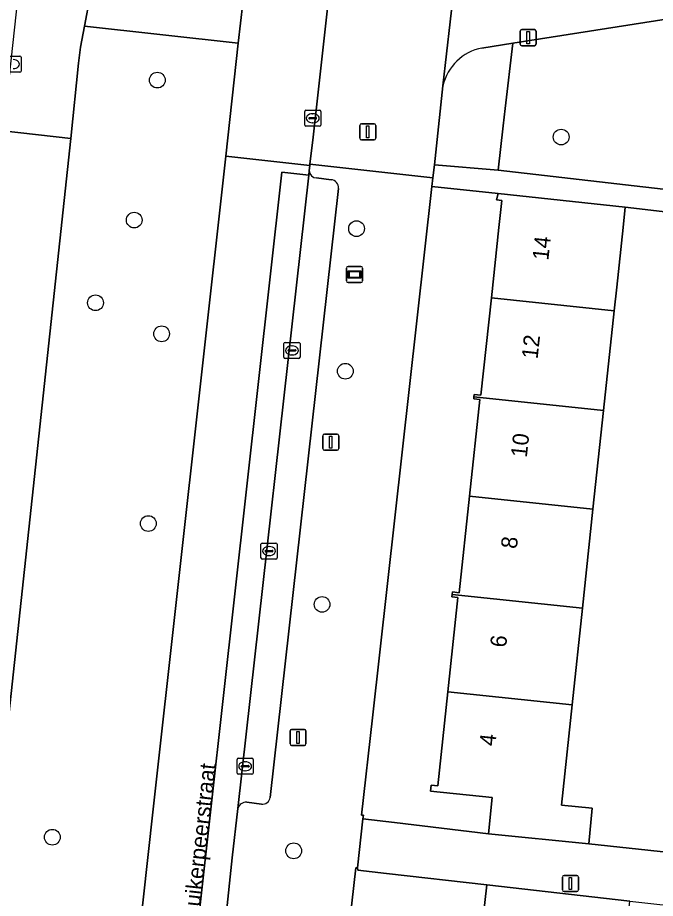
# Model space of a CAD drawing. Extents: x 162026 to 163502, y 387295 to 388169.
# Drawn here: x 162355 to 162394.6, y 387458.3 to 387513 of the extents above; entities that cross this region are included whole.
import ezdxf

# ---------------------------------------------------------------- set-up
doc = ezdxf.new("R2010")
doc.units = 0
for name, color, linetype in [('IMGEO_Berm_groen', 7, 'Continuous'), ('IMGEO_Boom', 7, 'Continuous'), ('IMGEO_Erf', 7, 'Continuous'), ('IMGEO_Fietspad_gesloten', 7, 'Continuous'), ('IMGEO_Groenvoorziening', 7, 'Continuous'), ('IMGEO_Hek', 7, 'Continuous'), ('IMGEO_Informatiebord', 7, 'Continuous'), ('IMGEO_Kolk', 7, 'Continuous'), ('IMGEO_Lichtmast', 7, 'Continuous'), ('IMGEO_Openbare_ruimte_label', 7, 'Continuous'), ('IMGEO_Pand', 7, 'Continuous'), ('IMGEO_Pand_nummerreeks', 7, 'Continuous'), ('IMGEO_Parkeervlak_open', 7, 'Continuous'), ('IMGEO_Rijbaan_lokaal_gesloten', 7, 'Continuous'), ('IMGEO_Voetpad_open', 7, 'Continuous')]:
    doc.layers.add(name, color=color, linetype=linetype)

msp = doc.modelspace()

# ---------------------------------------------------------------- linework, layer by layer
at = {"layer": 'IMGEO_Berm_groen'}
for points in [[(162367.963, 387504.443), (162368.74, 387511.448), (162359.196, 387512.511), (162358.952, 387511.213), (162358.817, 387510.216), (162358.349, 387505.53), (162353.961, 387464.714), (162349.86, 387427.109)], [(162361.255, 387443.988), (162363.465, 387463.887), (162367.963, 387504.443)]]:
    msp.add_lwpolyline(points, dxfattribs=at)
at = {"layer": 'IMGEO_Boom'}
for centre in [(162363.715, 387509.161), (162388.781, 387505.624), (162362.28, 387500.467), (162376.081, 387499.936), (162359.877, 387495.33), (162363.979, 387493.402), (162375.381, 387491.078), (162363.153, 387481.618), (162373.94, 387476.596), (162357.195, 387462.136), (162372.176, 387461.291)]:
    msp.add_circle(centre, 0.489, dxfattribs=at)
at = {"layer": 'IMGEO_Erf'}
msp.add_lwpolyline([(162383.737, 387489.316), (162383.352, 387489.357), (162383.367, 387489.498), (162383.382, 387489.641), (162383.805, 387489.596), (162384.45, 387495.645), (162384.914, 387500), (162385.095, 387501.693), (162384.765, 387501.728), (162384.875, 387502.11), (162380.76, 387502.548), (162377.073, 387469.561), (162376.396, 387463.513), (162376.503, 387463.509), (162376.477, 387463.277), (162378.441, 387463.04), (162384.272, 387462.336), (162384.492, 387464.596), (162380.664, 387465.004), (162380.704, 387465.377), (162381.127, 387465.332), (162381.75, 387471.175), (162382.373, 387477.018), (162382.003, 387477.058), (162382.02, 387477.215), (162382.037, 387477.369), (162382.459, 387477.324), (162383.098, 387483.32)], close=True, dxfattribs=at)
for points in [[(162399.996, 387500.421), (162392.758, 387501.269), (162392.623, 387500), (162392.228, 387496.298), (162392.072, 387494.832), (162391.411, 387488.64), (162390.757, 387482.503), (162390.101, 387476.353), (162389.461, 387470.353), (162388.798, 387464.131), (162390.708, 387463.945), (162390.492, 387461.729), (162395.498, 387461.182)], [(162377.752, 387439.384), (162379.017, 387439.241), (162379.247, 387441.236), (162378.017, 387441.378), (162378.471, 387445.326), (162378.919, 387449.221), (162380.223, 387449.071), (162380.463, 387451.159), (162381.147, 387457.113), (162383.889, 387456.798), (162384.164, 387459.183), (162377.94, 387459.884), (162376.15, 387460.086), (162376.131, 387460.234), (162376.03, 387460.239), (162375.655, 387456.942), (162371.134, 387416.396)]]:
    msp.add_lwpolyline(points, dxfattribs=at)
at = {"layer": 'IMGEO_Fietspad_gesloten'}
msp.add_lwpolyline([(162367.941, 387456.884), (162367.962, 387457.104), (162368.361, 387460.854), (162368.714, 387463.921), (162373.113, 387503.254), (162371.444, 387503.441), (162363.403, 387431.184)], dxfattribs=at)
at = {"layer": 'IMGEO_Groenvoorziening'}
msp.add_lwpolyline([(162404.551, 387514.406), (162385.791, 387511.457), (162385.309, 387507.39), (162385.183, 387506.312), (162384.868, 387503.561), (162403.028, 387501.478)], close=True, dxfattribs=at)
for points in [[(162385.309, 387507.39), (162385.791, 387511.457), (162383.865, 387511.154)], [(162381.44, 387508.812), (162380.999, 387504.686), (162380.911, 387503.894), (162384.868, 387503.561), (162385.183, 387506.312), (162385.309, 387507.39)]]:
    msp.add_lwpolyline(points, dxfattribs=at)
msp.add_arc((162384.455, 387508.117), 3.094, 100.9859, 167.0191, dxfattribs=at)
at = {"layer": 'IMGEO_Hek'}
msp.add_lwpolyline([(162384.868, 387503.561), (162385.791, 387511.457)], dxfattribs=at)
at = {"layer": 'IMGEO_Informatiebord'}
for p, q in [((162375.458, 387496.685), (162375.458, 387497.485)), ((162375.458, 387497.485), (162375.458, 387496.685)), ((162375.558, 387497.585), (162376.348, 387497.585)), ((162376.348, 387497.585), (162375.558, 387497.585)), ((162376.448, 387497.485), (162376.448, 387496.685)), ((162376.448, 387496.685), (162376.448, 387497.485)), ((162376.348, 387496.585), (162375.558, 387496.585)), ((162375.558, 387496.585), (162376.348, 387496.585))]:
    msp.add_line(p, q, dxfattribs=at)
for points in [[(162375.559, 387497.317), (162376.347, 387497.317), (162376.347, 387496.853), (162375.559, 387496.853), (162375.559, 387497.317)], [(162375.624, 387497.252), (162375.624, 387496.918), (162376.282, 387496.918), (162376.282, 387497.252), (162375.624, 387497.252)]]:
    msp.add_lwpolyline(points, dxfattribs=at)
for centre, start, end in [((162375.558, 387497.485), 90, 180), ((162375.558, 387497.485), 90, 180), ((162376.348, 387497.485), 0, 90), ((162376.348, 387497.485), 360, 90), ((162375.558, 387496.685), 180, 270), ((162375.558, 387496.685), 180, 270), ((162376.348, 387496.685), 270, 0), ((162376.348, 387496.685), 270, 0)]:
    msp.add_arc(centre, 0.1, start, end, dxfattribs=at)
at = {"layer": 'IMGEO_Kolk'}
for p, q in [((162354.327, 387510.652), (162355.179, 387510.652)), ((162355.253, 387510.578), (162355.253, 387509.726)), ((162355.179, 387509.652), (162354.327, 387509.652)), ((162372.861, 387506.367), (162372.861, 387507.219)), ((162372.936, 387507.293), (162373.788, 387507.293)), ((162373.862, 387507.219), (162373.862, 387506.367)), ((162373.12, 387506.787), (162373.12, 387506.799)), ((162373.558, 387506.75), (162373.16, 387506.75)), ((162373.163, 387506.836), (162373.561, 387506.836)), ((162373.349, 387507.073), (162373.374, 387507.073)), ((162373.604, 387506.799), (162373.604, 387506.787)), ((162373.788, 387506.293), (162372.936, 387506.293)), ((162373.372, 387506.513), (162373.347, 387506.513)), ((162371.569, 387491.945), (162371.569, 387492.797)), ((162371.644, 387492.871), (162372.496, 387492.871)), ((162372.057, 387492.651), (162372.082, 387492.651)), ((162372.57, 387492.797), (162372.57, 387491.945)), ((162371.828, 387492.365), (162371.828, 387492.377)), ((162372.266, 387492.328), (162371.868, 387492.328)), ((162371.871, 387492.414), (162372.269, 387492.414)), ((162372.08, 387492.091), (162372.055, 387492.091)), ((162372.312, 387492.377), (162372.312, 387492.365)), ((162372.496, 387491.871), (162371.644, 387491.871)), ((162370.222, 387480.409), (162371.074, 387480.409)), ((162370.147, 387479.483), (162370.147, 387480.335)), ((162370.406, 387479.903), (162370.406, 387479.915)), ((162370.844, 387479.866), (162370.446, 387479.866)), ((162370.449, 387479.952), (162370.847, 387479.952)), ((162370.635, 387480.189), (162370.66, 387480.189)), ((162370.89, 387479.915), (162370.89, 387479.903)), ((162371.148, 387480.335), (162371.148, 387479.483)), ((162371.074, 387479.409), (162370.222, 387479.409)), ((162370.658, 387479.629), (162370.633, 387479.629)), ((162368.663, 387466.118), (162368.663, 387466.97)), ((162368.738, 387467.044), (162369.59, 387467.044)), ((162369.151, 387466.824), (162369.176, 387466.824)), ((162369.664, 387466.97), (162369.664, 387466.118)), ((162368.922, 387466.538), (162368.922, 387466.55)), ((162369.36, 387466.501), (162368.962, 387466.501)), ((162368.965, 387466.587), (162369.363, 387466.587)), ((162369.174, 387466.264), (162369.149, 387466.264)), ((162369.406, 387466.55), (162369.406, 387466.538)), ((162369.59, 387466.044), (162368.738, 387466.044))]:
    msp.add_line(p, q, dxfattribs=at)
for points in [[(162354.327, 387510.652), (162355.179, 387510.652)], [(162355.253, 387510.578), (162355.253, 387509.726)], [(162355.179, 387509.652), (162354.327, 387509.652)], [(162372.861, 387506.367), (162372.861, 387507.219)], [(162372.936, 387507.293), (162373.788, 387507.293)], [(162373.862, 387507.219), (162373.862, 387506.367)], [(162373.788, 387506.293), (162372.936, 387506.293)], [(162371.569, 387491.945), (162371.569, 387492.797)], [(162371.644, 387492.871), (162372.496, 387492.871)], [(162372.57, 387492.797), (162372.57, 387491.945)], [(162372.496, 387491.871), (162371.644, 387491.871)], [(162370.222, 387480.409), (162371.074, 387480.409)], [(162370.147, 387479.483), (162370.147, 387480.335)], [(162371.148, 387480.335), (162371.148, 387479.483)], [(162371.074, 387479.409), (162370.222, 387479.409)], [(162368.663, 387466.118), (162368.663, 387466.97)], [(162368.738, 387467.044), (162369.59, 387467.044)], [(162369.664, 387466.97), (162369.664, 387466.118)], [(162369.59, 387466.044), (162368.738, 387466.044)]]:
    msp.add_lwpolyline(points, dxfattribs=at)
for centre, radius, start, end in [((162355.177, 387510.576), 0.0765, 1.552, 88.448), ((162355.177, 387510.576), 0.0765, 1.552, 88.448), ((162355.177, 387509.728), 0.0765, 271.552, 358.448), ((162355.177, 387509.728), 0.0765, 271.552, 358.448), ((162372.938, 387507.217), 0.0765, 91.552, 178.448), ((162372.938, 387507.217), 0.0765, 91.552, 178.448), ((162373.786, 387507.217), 0.0765, 1.552, 88.448), ((162373.786, 387507.217), 0.0765, 1.552, 88.448), ((162373.16, 387506.796), 0.0403, 85.8775, 175.7526), ((162373.157, 387506.786), 0.0366, 178.938, 274.7102), ((162373.561, 387506.793), 0.043, 264.8664, 352.4533), ((162373.565, 387506.798), 0.0386, 1.7309, 96.639), ((162372.938, 387506.369), 0.0765, 181.552, 268.448), ((162372.938, 387506.369), 0.0765, 181.552, 268.448), ((162373.786, 387506.369), 0.0765, 271.552, 358.448), ((162373.786, 387506.369), 0.0765, 271.552, 358.448), ((162371.646, 387492.795), 0.0765, 91.552, 178.448), ((162371.646, 387492.795), 0.0765, 91.552, 178.448), ((162372.494, 387492.795), 0.0765, 1.552, 88.448), ((162372.494, 387492.795), 0.0765, 1.552, 88.448), ((162371.646, 387491.947), 0.0765, 181.552, 268.448), ((162371.646, 387491.947), 0.0765, 181.552, 268.448), ((162371.868, 387492.374), 0.0403, 85.8775, 175.7526), ((162371.865, 387492.364), 0.0366, 178.938, 274.7102), ((162372.269, 387492.371), 0.043, 264.8664, 352.4533), ((162372.273, 387492.376), 0.0386, 1.7309, 96.639), ((162372.494, 387491.947), 0.0765, 271.552, 358.448), ((162372.494, 387491.947), 0.0765, 271.552, 358.448), ((162370.224, 387480.333), 0.0765, 91.552, 178.448), ((162370.224, 387480.333), 0.0765, 91.552, 178.448), ((162371.072, 387480.333), 0.0765, 1.552, 88.448), ((162371.072, 387480.333), 0.0765, 1.552, 88.448), ((162370.446, 387479.912), 0.0403, 85.8775, 175.7526), ((162370.443, 387479.902), 0.0366, 178.938, 274.7102), ((162370.847, 387479.909), 0.043, 264.8664, 352.4533), ((162370.851, 387479.914), 0.0386, 1.7309, 96.639), ((162370.224, 387479.485), 0.0765, 181.552, 268.448), ((162370.224, 387479.485), 0.0765, 181.552, 268.448), ((162371.072, 387479.485), 0.0765, 271.552, 358.448), ((162371.072, 387479.485), 0.0765, 271.552, 358.448), ((162368.74, 387466.968), 0.0765, 91.552, 178.448), ((162368.74, 387466.968), 0.0765, 91.552, 178.448), ((162369.588, 387466.968), 0.0765, 1.552, 88.448), ((162369.588, 387466.968), 0.0765, 1.552, 88.448), ((162368.962, 387466.547), 0.0403, 85.8775, 175.7526), ((162368.959, 387466.537), 0.0366, 178.938, 274.7102), ((162369.363, 387466.544), 0.043, 264.8664, 352.4533), ((162369.367, 387466.549), 0.0386, 1.7309, 96.639), ((162368.74, 387466.12), 0.0765, 181.552, 268.448), ((162368.74, 387466.12), 0.0765, 181.552, 268.448), ((162369.588, 387466.12), 0.0765, 271.552, 358.448), ((162369.588, 387466.12), 0.0765, 271.552, 358.448)]:
    msp.add_arc(centre, radius, start, end, dxfattribs=at)
for centre, major_axis, ratio, start_param, end_param in [((162354.764, 387510.152), (-0.39, 0.002), 0.717154, 1.570796, 4.712389), ((162373.348, 387506.793), (-0.387, 0.002), 0.722429, 4.712389, 7.853982), ((162373.373, 387506.793), (-0.39, 0.002), 0.717154, 1.570796, 4.712389), ((162372.056, 387492.371), (-0.387, 0.002), 0.722429, 4.712389, 7.853982), ((162372.081, 387492.371), (-0.39, 0.002), 0.717154, 1.570796, 4.712389), ((162370.634, 387479.909), (-0.387, 0.002), 0.722429, 4.712389, 7.853982), ((162370.659, 387479.909), (-0.39, 0.002), 0.717154, 1.570796, 4.712389), ((162369.15, 387466.544), (-0.387, 0.002), 0.722429, 4.712389, 7.853982), ((162369.175, 387466.544), (-0.39, 0.002), 0.717154, 1.570796, 4.712389)]:
    msp.add_ellipse(centre, major_axis=major_axis, ratio=ratio, start_param=start_param, end_param=end_param, dxfattribs=at)
at = {"layer": 'IMGEO_Lichtmast'}
for p, q in [((162386.237, 387511.396), (162386.237, 387512.196)), ((162386.237, 387512.196), (162386.237, 387511.396)), ((162386.337, 387512.296), (162387.127, 387512.296)), ((162387.127, 387512.296), (162386.337, 387512.296)), ((162387.227, 387512.196), (162387.227, 387511.396)), ((162387.227, 387511.396), (162387.227, 387512.196)), ((162387.127, 387511.296), (162386.337, 387511.296)), ((162386.337, 387511.296), (162387.127, 387511.296)), ((162376.278, 387505.546), (162376.278, 387506.346)), ((162376.278, 387506.346), (162376.278, 387505.546)), ((162376.378, 387506.446), (162377.168, 387506.446)), ((162377.168, 387506.446), (162376.378, 387506.446)), ((162377.268, 387506.346), (162377.268, 387505.546)), ((162377.268, 387505.546), (162377.268, 387506.346)), ((162377.168, 387505.446), (162376.378, 387505.446)), ((162376.378, 387505.446), (162377.168, 387505.446)), ((162373.982, 387486.276), (162373.982, 387487.076)), ((162373.982, 387487.076), (162373.982, 387486.276)), ((162374.082, 387487.176), (162374.872, 387487.176)), ((162374.872, 387487.176), (162374.082, 387487.176)), ((162374.972, 387487.076), (162374.972, 387486.276)), ((162374.972, 387486.276), (162374.972, 387487.076)), ((162374.872, 387486.176), (162374.082, 387486.176)), ((162374.082, 387486.176), (162374.872, 387486.176)), ((162371.952, 387467.934), (162371.952, 387468.734)), ((162371.952, 387468.734), (162371.952, 387467.934)), ((162372.052, 387468.834), (162372.842, 387468.834)), ((162372.842, 387468.834), (162372.052, 387468.834)), ((162372.942, 387468.734), (162372.942, 387467.934)), ((162372.942, 387467.934), (162372.942, 387468.734)), ((162372.842, 387467.834), (162372.052, 387467.834)), ((162372.052, 387467.834), (162372.842, 387467.834)), ((162388.86, 387458.865), (162388.86, 387459.665)), ((162388.86, 387459.665), (162388.86, 387458.865)), ((162388.96, 387459.765), (162389.75, 387459.765)), ((162389.75, 387459.765), (162388.96, 387459.765)), ((162389.85, 387459.665), (162389.85, 387458.865)), ((162389.85, 387458.865), (162389.85, 387459.665)), ((162389.75, 387458.765), (162388.96, 387458.765)), ((162388.96, 387458.765), (162389.75, 387458.765))]:
    msp.add_line(p, q, dxfattribs=at)
for points in [[(162386.657, 387512.171), (162386.807, 387512.171), (162386.807, 387511.421), (162386.657, 387511.421), (162386.657, 387512.171)], [(162376.698, 387506.321), (162376.848, 387506.321), (162376.848, 387505.571), (162376.698, 387505.571), (162376.698, 387506.321)], [(162374.402, 387487.051), (162374.552, 387487.051), (162374.552, 387486.301), (162374.402, 387486.301), (162374.402, 387487.051)], [(162372.372, 387468.709), (162372.522, 387468.709), (162372.522, 387467.959), (162372.372, 387467.959), (162372.372, 387468.709)], [(162389.28, 387459.64), (162389.43, 387459.64), (162389.43, 387458.89), (162389.28, 387458.89), (162389.28, 387459.64)]]:
    msp.add_lwpolyline(points, dxfattribs=at)
for centre, start, end in [((162386.337, 387512.196), 90, 180), ((162386.337, 387512.196), 90, 180), ((162387.127, 387512.196), 0, 90), ((162387.127, 387512.196), 360, 90), ((162386.337, 387511.396), 180, 270), ((162386.337, 387511.396), 180, 270), ((162387.127, 387511.396), 270, 0), ((162387.127, 387511.396), 270, 0), ((162376.378, 387506.346), 90, 180), ((162376.378, 387506.346), 90, 180), ((162377.168, 387506.346), 0, 90), ((162377.168, 387506.346), 360, 90), ((162376.378, 387505.546), 180, 270), ((162376.378, 387505.546), 180, 270), ((162377.168, 387505.546), 270, 0), ((162377.168, 387505.546), 270, 0), ((162374.082, 387487.076), 90, 180), ((162374.082, 387487.076), 90, 180), ((162374.872, 387487.076), 0, 90), ((162374.872, 387487.076), 360, 90), ((162374.082, 387486.276), 180, 270), ((162374.082, 387486.276), 180, 270), ((162374.872, 387486.276), 270, 0), ((162374.872, 387486.276), 270, 0), ((162372.052, 387468.734), 90, 180), ((162372.052, 387468.734), 90, 180), ((162372.842, 387468.734), 0, 90), ((162372.842, 387468.734), 360, 90), ((162372.052, 387467.934), 180, 270), ((162372.052, 387467.934), 180, 270), ((162372.842, 387467.934), 270, 0), ((162372.842, 387467.934), 270, 0), ((162388.96, 387459.665), 90, 180), ((162388.96, 387459.665), 90, 180), ((162389.75, 387459.665), 0, 90), ((162389.75, 387459.665), 360, 90), ((162388.96, 387458.865), 180, 270), ((162388.96, 387458.865), 180, 270), ((162389.75, 387458.865), 270, 0), ((162389.75, 387458.865), 270, 0)]:
    msp.add_arc(centre, 0.1, start, end, dxfattribs=at)
at = {"layer": 'IMGEO_Pand'}
for points in [[(162392.072, 387494.832), (162392.228, 387496.298), (162392.623, 387500), (162392.758, 387501.269), (162384.875, 387502.11), (162384.765, 387501.728), (162385.095, 387501.693), (162384.914, 387500), (162384.45, 387495.645)], [(162391.411, 387488.64), (162392.072, 387494.832), (162384.45, 387495.645), (162383.805, 387489.596), (162383.382, 387489.641), (162383.367, 387489.498)], [(162383.367, 387489.498), (162383.352, 387489.357), (162383.737, 387489.316), (162383.098, 387483.32), (162390.757, 387482.503), (162391.411, 387488.64)], [(162383.098, 387483.32), (162382.459, 387477.324), (162382.037, 387477.369), (162382.02, 387477.215), (162390.101, 387476.353), (162390.757, 387482.503)], [(162389.461, 387470.353), (162390.101, 387476.353), (162382.02, 387477.215), (162382.003, 387477.058), (162382.373, 387477.018), (162381.75, 387471.175)], [(162390.492, 387461.729), (162390.708, 387463.945), (162388.798, 387464.131), (162389.461, 387470.353), (162381.75, 387471.175), (162381.127, 387465.332), (162380.704, 387465.377), (162380.664, 387465.004), (162384.492, 387464.596), (162384.272, 387462.336)], [(162392.061, 387455.86), (162392.771, 387455.778), (162393.046, 387458.163), (162384.164, 387459.183), (162383.889, 387456.798), (162381.147, 387457.113), (162380.463, 387451.159), (162388.505, 387450.25), (162391.38, 387449.925)]]:
    msp.add_lwpolyline(points, close=True, dxfattribs=at)
at = {"layer": 'IMGEO_Parkeervlak_open'}
for points in [[(162373.146, 387503.547), (162373.113, 387503.254), (162368.714, 387463.921)], [(162374.499, 387502.974), (162373.599, 387503.081)], [(162370.714, 387464.613), (162374.956, 387502.431)], [(162369.271, 387464.303), (162370.174, 387464.192)]]:
    msp.add_lwpolyline(points, dxfattribs=at)
for centre, radius, start, end in [((162373.612, 387503.547), 0.466, 180.0238, 268.3553), ((162374.464, 387502.481), 0.494, 354.1821, 85.9872), ((162370.244, 387464.659), 0.473, 261.5146, 354.3674), ((162369.214, 387463.789), 0.518, 83.7168, 165.1692)]:
    msp.add_arc(centre, radius, start, end, dxfattribs=at)
at = {"layer": 'IMGEO_Rijbaan_lokaal_gesloten'}
for points in [[(162356.277, 387525.641), (162354.736, 387511.489), (162354.384, 387508.263), (162354.328, 387507.743), (162354.15, 387506.017), (162358.349, 387505.53), (162358.817, 387510.216), (162358.952, 387511.213), (162359.196, 387512.511), (162359.887, 387516.261), (162362.107, 387528.18)], [(162369.24, 387516.173), (162369.161, 387515.205), (162368.74, 387511.448), (162367.963, 387504.443), (162373.181, 387503.861), (162373.19, 387503.935), (162373.382, 387505.621), (162375.378, 387523.498)], [(162371.444, 387503.441), (162373.113, 387503.254), (162373.146, 387503.547), (162373.181, 387503.861), (162367.963, 387504.443), (162363.465, 387463.887), (162361.255, 387443.988)], [(162363.403, 387431.184), (162371.444, 387503.441)]]:
    msp.add_lwpolyline(points, dxfattribs=at)
msp.add_lwpolyline([(162353.961, 387464.714), (162358.349, 387505.53), (162354.15, 387506.017), (162353.924, 387503.81), (162353.243, 387497.608), (162353.136, 387496.605), (162352.335, 387489.102), (162352.257, 387488.34), (162349.834, 387466.006), (162349.065, 387458.811), (162348.272, 387451.322), (162348.127, 387450.097), (162347.103, 387440.899), (162346.475, 387434.916), (162346.314, 387433.695), (162345.649, 387427.488), (162345.245, 387423.574), (162349.464, 387424), (162349.86, 387427.109)], close=True, dxfattribs=at)
at = {"layer": 'IMGEO_Voetpad_open'}
for points in [[(162375.378, 387523.498), (162373.382, 387505.621), (162373.19, 387503.935), (162380.82, 387503.083), (162380.911, 387503.894), (162380.999, 387504.686), (162381.44, 387508.812), (162382.349, 387516.776)], [(162383.865, 387511.154), (162385.791, 387511.457), (162404.551, 387514.406), (162408.822, 387515.078), (162409.124, 387515.071), (162411.844, 387514.804), (162442.75, 387511.59), (162443.453, 387517.421), (162480.419, 387513.193), (162481.197, 387519.204), (162500, 387517.178), (162518.432, 387515.192)], [(162382.349, 387516.776), (162381.44, 387508.812)], [(162376.477, 387463.277), (162376.503, 387463.509), (162376.396, 387463.513), (162377.073, 387469.561), (162380.76, 387502.548), (162380.82, 387503.083), (162373.19, 387503.935), (162373.181, 387503.861), (162373.146, 387503.547)], [(162403.028, 387501.478), (162384.868, 387503.561), (162380.911, 387503.894), (162380.82, 387503.083), (162380.76, 387502.548), (162384.875, 387502.11), (162392.758, 387501.269), (162399.996, 387500.421)], [(162373.599, 387503.081), (162374.499, 387502.974)], [(162374.956, 387502.431), (162370.714, 387464.613)], [(162370.174, 387464.192), (162369.271, 387464.303)], [(162368.714, 387463.921), (162368.361, 387460.854), (162367.962, 387457.104), (162367.941, 387456.884), (162365.797, 387437.657)], [(162367.108, 387422.786), (162367.19, 387421.816), (162366.853, 387417.815), (162371.134, 387416.396), (162375.655, 387456.942), (162376.03, 387460.239), (162376.131, 387460.234), (162376.477, 387463.277)]]:
    msp.add_lwpolyline(points, dxfattribs=at)
for points in [[(162369.161, 387515.205), (162359.887, 387516.261), (162359.196, 387512.511), (162368.74, 387511.448)], [(162400.124, 387460.686), (162398.668, 387460.844), (162395.498, 387461.182), (162390.492, 387461.729), (162384.272, 387462.336), (162378.441, 387463.04), (162376.477, 387463.277), (162376.131, 387460.234), (162376.15, 387460.086), (162377.94, 387459.884), (162384.164, 387459.183), (162393.046, 387458.163), (162401.278, 387457.263), (162403.987, 387456.967), (162459.816, 387450.863), (162459.98, 387453.961), (162433.518, 387457.07)]]:
    msp.add_lwpolyline(points, close=True, dxfattribs=at)
for centre, radius, start, end in [((162384.455, 387508.117), 3.094, 100.9859, 167.0191), ((162373.612, 387503.547), 0.466, 180.0238, 268.3553), ((162374.464, 387502.481), 0.494, 354.1821, 85.9872), ((162370.244, 387464.659), 0.473, 261.5146, 354.3674), ((162369.214, 387463.789), 0.518, 83.7168, 165.1692)]:
    msp.add_arc(centre, radius, start, end, dxfattribs=at)

# ---------------------------------------------------------------- texts
at = {"layer": 'IMGEO_Openbare_ruimte_label'}
msp.add_text('Suikerpeerstraat', height=1, rotation=83.7421, dxfattribs=at).set_placement((162366.28, 387456.916))
at = {"layer": 'IMGEO_Pand_nummerreeks'}
for s, p in [('14', (162387.984, 387497.933)), ('12', (162387.316, 387491.805)), ('10', (162386.647, 387485.686)), ('8', (162386.029, 387480.019)), ('6', (162385.36, 387473.89)), ('4', (162384.692, 387467.765))]:
    msp.add_text(s, height=1, rotation=83.7721, dxfattribs=at).set_placement(p)

doc.saveas('drawing.dxf')
